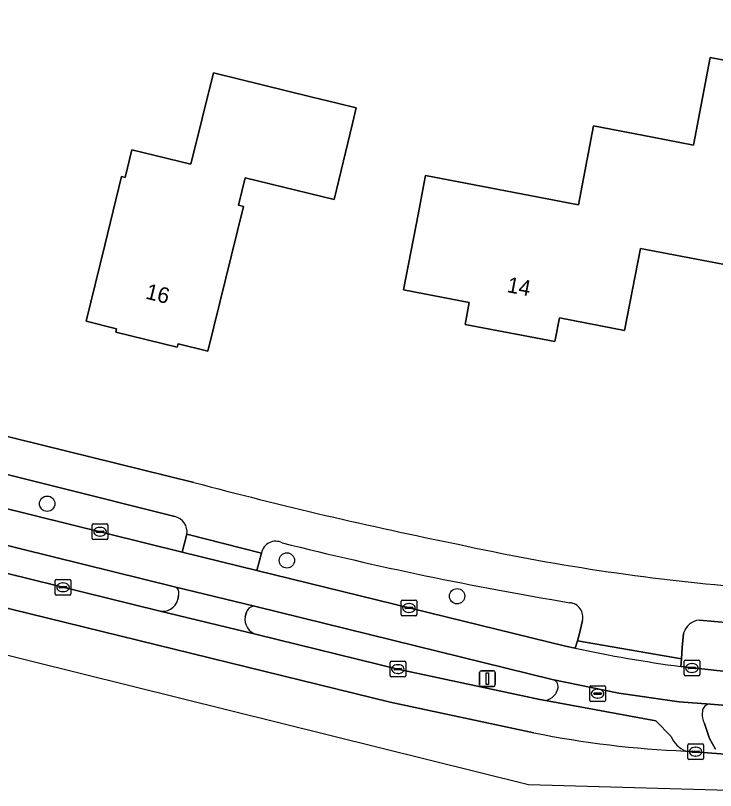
# Model space of a CAD drawing. Extents: x 161347 to 161881, y 382161 to 382804.
# Drawn here: x 161529.3 to 161573.93, y 382161.25 to 382210.69 of the extents above; entities that cross this region are included whole.
import ezdxf

# ---------------------------------------------------------------- set-up
doc = ezdxf.new("R2010")
doc.units = 0
for name, color, linetype in [('IMGEO_Berm_groen', 7, 'Continuous'), ('IMGEO_Boom', 7, 'Continuous'), ('IMGEO_Erf', 7, 'Continuous'), ('IMGEO_Fietspad_gesloten', 7, 'Continuous'), ('IMGEO_Kolk', 7, 'Continuous'), ('IMGEO_Lichtmast', 7, 'Continuous'), ('IMGEO_Pand', 7, 'Continuous'), ('IMGEO_Pand_nummerreeks', 7, 'Continuous'), ('IMGEO_Parkeervlak_gesloten', 7, 'Continuous'), ('IMGEO_Rijbaan_lokaal_gesloten', 7, 'Continuous'), ('IMGEO_Rioolput', 7, 'Continuous'), ('IMGEO_Verkeerseiland_open', 7, 'Continuous'), ('IMGEO_Voetpad_open', 7, 'Continuous')]:
    doc.layers.add(name, color=color, linetype=linetype)

msp = doc.modelspace()

# ---------------------------------------------------------------- linework, layer by layer
at = {"layer": 'IMGEO_Berm_groen'}
for points in [[(161523.76, 382182.658), (161523.26, 382180.579), (161539.929, 382176.444), (161540.229, 382177.6)], [(161539.452, 382178.724), (161523.76, 382182.658)], [(161539.444, 382174.246), (161523.769, 382178.11)], [(161523.782, 382176.315), (161538.439, 382172.703)], [(161544.988, 382176.392), (161544.687, 382175.272), (161564.377, 382170.458), (161564.988, 382170.326), (161565.131, 382170.805), (161565.266, 382171.258), (161565.458, 382172.096)], [(161539.66, 382173.423), (161539.695, 382173.695)], [(161563.516, 382168.335), (161544.627, 382172.985)], [(161544.032, 382172.631), (161543.946, 382172.356)], [(161575.793, 382171.854), (161572.905, 382172.115)], [(161571.905, 382171.267), (161571.81, 382170.378), (161571.757, 382169.655), (161571.72, 382169.156), (161576.527, 382168.636), (161576.563, 382169.135), (161576.609, 382169.787), (161576.631, 382170.705)], [(161544.683, 382171.197), (161553.68, 382168.99), (161562.741, 382167.053), (161563.09, 382166.989)]]:
    msp.add_lwpolyline(points, dxfattribs=at)
for centre, radius, start, end in [((161539.245, 382177.75), 0.996, 351.3225, 77.9882), ((161545.893, 382176.228), 0.92, 62.9734, 169.7054), ((161602.441, 382400.592), 230.484, 255.90508, 260.56483), ((161539.305, 382173.85), 0.419, 338.2981, 70.6838), ((161538.669, 382173.708), 1.031, 257.1038, 343.9503), ((161564.552, 382172.302), 0.93, 347.1697, 83.4921), ((161544.517, 382172.492), 0.505, 77.4373, 164.0644), ((161544.932, 382172.169), 1.004, 169.2756, 255.6284), ((161573.004, 382170.985), 1.135, 94.9994, 165.5965), ((161563.409, 382167.844), 0.503, 356.6377, 77.698), ((161562.887, 382168.012), 1.043, 281.2179, 349.0606)]:
    msp.add_arc(centre, radius, start, end, dxfattribs=at)
at = {"layer": 'IMGEO_Boom'}
for centre in [(161531.321, 382179.543), (161546.606, 382175.923), (161557.458, 382173.643)]:
    msp.add_circle(centre, 0.489, dxfattribs=at)
at = {"layer": 'IMGEO_Erf'}
msp.add_lwpolyline([(161420.378, 382210.687), (161464.013, 382199.817), (161500, 382190.938), (161540.678, 382180.901)], dxfattribs=at)
for points in [[(161577.039, 382198.776), (161575.33, 382199.104), (161574.504, 382194.801), (161569.143, 382195.829), (161568.139, 382190.598), (161563.988, 382191.395), (161563.698, 382189.886), (161557.969, 382190.985), (161558.235, 382192.373), (161554.045, 382193.177), (161554.988, 382198.088), (161555.341, 382199.93), (161555.448, 382200.485), (161565.196, 382198.605), (161566.163, 382203.645), (161569.916, 382202.925), (161572.525, 382202.424), (161573.599, 382208.016), (161577.829, 382207.204)], [(161549.617, 382198.942), (161543.945, 382200.333), (161543.516, 382198.584), (161543.836, 382198.505), (161541.572, 382189.278), (161539.668, 382189.745), (161539.615, 382189.531), (161535.693, 382190.494), (161535.745, 382190.707), (161533.802, 382191.184), (161534.993, 382196.041), (161536.065, 382200.41), (161536.289, 382200.356), (161536.723, 382202.124), (161540.492, 382201.2), (161541.922, 382207.028), (161548.222, 382205.483), (161549.805, 382205.095), (161551.032, 382204.794), (161550.792, 382203.802)]]:
    msp.add_lwpolyline(points, close=True, dxfattribs=at)
for centre, radius, start, end in [((161612.703, 382450.618), 279.168, 255.04873, 258.59958), ((161586.624, 382308.838), 135.053, 257.55552, 265.3213)]:
    msp.add_arc(centre, radius, start, end, dxfattribs=at)
at = {"layer": 'IMGEO_Fietspad_gesloten'}
for points in [[(161413.236, 382205.52), (161415.308, 382205.003), (161418.403, 382204.211), (161448.631, 382196.696), (161453.454, 382195.498), (161462.581, 382193.233), (161478.779, 382189.246), (161484.015, 382187.92), (161495.709, 382185.028), (161500, 382183.961), (161501.342, 382183.627), (161519.01, 382179.306), (161523.769, 382178.11), (161539.444, 382174.246), (161544.627, 382172.985), (161563.516, 382168.335), (161567.78, 382167.465), (161571.619, 382166.9), (161573.608, 382166.754), (161575.893, 382166.568), (161576.527, 382168.636), (161571.72, 382169.156)], [(161564.988, 382170.326), (161564.377, 382170.458), (161544.687, 382175.272), (161539.929, 382176.444), (161523.26, 382180.579), (161517.367, 382182.012), (161501.233, 382185.995)]]:
    msp.add_lwpolyline(points, dxfattribs=at)
msp.add_arc((161583.507, 382256.929), 88.561, 257.92979, 262.35153, dxfattribs=at)
at = {"layer": 'IMGEO_Kolk'}
for p, q in [((161534.194, 382177.329), (161534.194, 382178.181)), ((161534.269, 382178.255), (161535.121, 382178.255)), ((161535.195, 382178.181), (161535.195, 382177.329)), ((161534.453, 382177.749), (161534.453, 382177.761)), ((161534.891, 382177.712), (161534.493, 382177.712)), ((161534.496, 382177.798), (161534.894, 382177.798)), ((161534.682, 382178.035), (161534.707, 382178.035)), ((161534.937, 382177.761), (161534.937, 382177.749)), ((161535.121, 382177.255), (161534.269, 382177.255)), ((161534.705, 382177.475), (161534.68, 382177.475)), ((161531.908, 382174.711), (161532.76, 382174.711)), ((161531.833, 382173.785), (161531.833, 382174.637)), ((161532.092, 382174.205), (161532.092, 382174.217)), ((161532.135, 382174.254), (161532.533, 382174.254)), ((161532.321, 382174.491), (161532.346, 382174.491)), ((161532.576, 382174.217), (161532.576, 382174.205)), ((161532.834, 382174.637), (161532.834, 382173.785)), ((161532.76, 382173.711), (161531.908, 382173.711)), ((161532.53, 382174.168), (161532.132, 382174.168)), ((161532.344, 382173.931), (161532.319, 382173.931)), ((161553.888, 382172.464), (161553.888, 382173.316)), ((161553.963, 382173.39), (161554.815, 382173.39)), ((161554.889, 382173.316), (161554.889, 382172.464)), ((161554.147, 382172.884), (161554.147, 382172.896)), ((161554.585, 382172.847), (161554.187, 382172.847)), ((161554.19, 382172.933), (161554.588, 382172.933)), ((161554.376, 382173.17), (161554.401, 382173.17)), ((161554.631, 382172.896), (161554.631, 382172.884)), ((161554.815, 382172.39), (161553.963, 382172.39)), ((161554.399, 382172.61), (161554.374, 382172.61)), ((161553.183, 382168.565), (161553.183, 382169.417)), ((161553.258, 382169.491), (161554.11, 382169.491)), ((161553.671, 382169.271), (161553.696, 382169.271)), ((161554.184, 382169.417), (161554.184, 382168.565)), ((161571.93, 382168.638), (161571.93, 382169.49)), ((161572.005, 382169.564), (161572.857, 382169.564)), ((161572.418, 382169.344), (161572.443, 382169.344)), ((161572.931, 382169.49), (161572.931, 382168.638)), ((161553.442, 382168.985), (161553.442, 382168.997)), ((161553.88, 382168.948), (161553.482, 382168.948)), ((161553.485, 382169.034), (161553.883, 382169.034)), ((161553.926, 382168.997), (161553.926, 382168.985)), ((161572.189, 382169.058), (161572.189, 382169.07)), ((161572.627, 382169.021), (161572.229, 382169.021)), ((161572.232, 382169.107), (161572.63, 382169.107)), ((161572.441, 382168.784), (161572.416, 382168.784)), ((161572.673, 382169.07), (161572.673, 382169.058)), ((161554.11, 382168.491), (161553.258, 382168.491)), ((161553.694, 382168.711), (161553.669, 382168.711)), ((161572.857, 382168.564), (161572.005, 382168.564)), ((161572.163, 382163.297), (161572.163, 382164.149)), ((161572.238, 382164.223), (161573.09, 382164.223)), ((161572.651, 382164.003), (161572.676, 382164.003)), ((161573.164, 382164.149), (161573.164, 382163.297)), ((161572.422, 382163.717), (161572.422, 382163.729)), ((161572.86, 382163.68), (161572.462, 382163.68)), ((161572.465, 382163.766), (161572.863, 382163.766)), ((161572.674, 382163.443), (161572.649, 382163.443)), ((161572.906, 382163.729), (161572.906, 382163.717)), ((161573.09, 382163.223), (161572.238, 382163.223))]:
    msp.add_line(p, q, dxfattribs=at)
for points in [[(161534.194, 382177.329), (161534.194, 382178.181)], [(161534.269, 382178.255), (161535.121, 382178.255)], [(161535.195, 382178.181), (161535.195, 382177.329)], [(161535.121, 382177.255), (161534.269, 382177.255)], [(161531.908, 382174.711), (161532.76, 382174.711)], [(161531.833, 382173.785), (161531.833, 382174.637)], [(161532.834, 382174.637), (161532.834, 382173.785)], [(161532.76, 382173.711), (161531.908, 382173.711)], [(161553.888, 382172.464), (161553.888, 382173.316)], [(161553.963, 382173.39), (161554.815, 382173.39)], [(161554.889, 382173.316), (161554.889, 382172.464)], [(161554.815, 382172.39), (161553.963, 382172.39)], [(161553.183, 382168.565), (161553.183, 382169.417)], [(161553.258, 382169.491), (161554.11, 382169.491)], [(161554.184, 382169.417), (161554.184, 382168.565)], [(161571.93, 382168.638), (161571.93, 382169.49)], [(161572.005, 382169.564), (161572.857, 382169.564)], [(161572.931, 382169.49), (161572.931, 382168.638)], [(161554.11, 382168.491), (161553.258, 382168.491)], [(161572.857, 382168.564), (161572.005, 382168.564)], [(161572.163, 382163.297), (161572.163, 382164.149)], [(161572.238, 382164.223), (161573.09, 382164.223)], [(161573.164, 382164.149), (161573.164, 382163.297)], [(161573.09, 382163.223), (161572.238, 382163.223)]]:
    msp.add_lwpolyline(points, dxfattribs=at)
for centre, radius, start, end in [((161534.271, 382178.179), 0.0765, 91.552, 178.448), ((161534.271, 382178.179), 0.0765, 91.552, 178.448), ((161535.119, 382178.179), 0.0765, 1.552, 88.448), ((161535.119, 382178.179), 0.0765, 1.552, 88.448), ((161534.493, 382177.758), 0.0403, 85.8775, 175.7526), ((161534.49, 382177.748), 0.0366, 178.938, 274.7102), ((161534.894, 382177.755), 0.043, 264.8664, 352.4533), ((161534.898, 382177.76), 0.0386, 1.7309, 96.639), ((161534.271, 382177.331), 0.0765, 181.552, 268.448), ((161534.271, 382177.331), 0.0765, 181.552, 268.448), ((161535.119, 382177.331), 0.0765, 271.552, 358.448), ((161535.119, 382177.331), 0.0765, 271.552, 358.448), ((161531.91, 382174.635), 0.0765, 91.552, 178.448), ((161531.91, 382174.635), 0.0765, 91.552, 178.448), ((161532.758, 382174.635), 0.0765, 1.552, 88.448), ((161532.758, 382174.635), 0.0765, 1.552, 88.448), ((161532.132, 382174.214), 0.0403, 85.8775, 175.7526), ((161532.129, 382174.204), 0.0366, 178.938, 274.7102), ((161532.533, 382174.211), 0.043, 264.8664, 352.4533), ((161532.537, 382174.216), 0.0386, 1.7309, 96.639), ((161531.91, 382173.787), 0.0765, 181.552, 268.448), ((161531.91, 382173.787), 0.0765, 181.552, 268.448), ((161532.758, 382173.787), 0.0765, 271.552, 358.448), ((161532.758, 382173.787), 0.0765, 271.552, 358.448), ((161553.965, 382173.314), 0.0765, 91.552, 178.448), ((161553.965, 382173.314), 0.0765, 91.552, 178.448), ((161554.813, 382173.314), 0.0765, 1.552, 88.448), ((161554.813, 382173.314), 0.0765, 1.552, 88.448), ((161554.187, 382172.893), 0.0403, 85.8775, 175.7526), ((161554.184, 382172.883), 0.0366, 178.938, 274.7102), ((161554.588, 382172.89), 0.043, 264.8664, 352.4533), ((161554.592, 382172.895), 0.0386, 1.7309, 96.639), ((161553.965, 382172.466), 0.0765, 181.552, 268.448), ((161553.965, 382172.466), 0.0765, 181.552, 268.448), ((161554.813, 382172.466), 0.0765, 271.552, 358.448), ((161554.813, 382172.466), 0.0765, 271.552, 358.448), ((161553.26, 382169.415), 0.0765, 91.552, 178.448), ((161553.26, 382169.415), 0.0765, 91.552, 178.448), ((161554.108, 382169.415), 0.0765, 1.552, 88.448), ((161554.108, 382169.415), 0.0765, 1.552, 88.448), ((161572.007, 382169.488), 0.0765, 91.552, 178.448), ((161572.007, 382169.488), 0.0765, 91.552, 178.448), ((161572.855, 382169.488), 0.0765, 1.552, 88.448), ((161572.855, 382169.488), 0.0765, 1.552, 88.448), ((161553.482, 382168.994), 0.0403, 85.8775, 175.7526), ((161553.479, 382168.984), 0.0366, 178.938, 274.7102), ((161553.883, 382168.991), 0.043, 264.8664, 352.4533), ((161553.887, 382168.996), 0.0386, 1.7309, 96.639), ((161572.229, 382169.067), 0.0403, 85.8775, 175.7526), ((161572.226, 382169.057), 0.0366, 178.938, 274.7102), ((161572.63, 382169.064), 0.043, 264.8664, 352.4533), ((161572.634, 382169.069), 0.0386, 1.7309, 96.639), ((161553.26, 382168.567), 0.0765, 181.552, 268.448), ((161553.26, 382168.567), 0.0765, 181.552, 268.448), ((161554.108, 382168.567), 0.0765, 271.552, 358.448), ((161554.108, 382168.567), 0.0765, 271.552, 358.448), ((161572.007, 382168.64), 0.0765, 181.552, 268.448), ((161572.007, 382168.64), 0.0765, 181.552, 268.448), ((161572.855, 382168.64), 0.0765, 271.552, 358.448), ((161572.855, 382168.64), 0.0765, 271.552, 358.448), ((161572.24, 382164.147), 0.0765, 91.552, 178.448), ((161572.24, 382164.147), 0.0765, 91.552, 178.448), ((161573.088, 382164.147), 0.0765, 1.552, 88.448), ((161573.088, 382164.147), 0.0765, 1.552, 88.448), ((161572.462, 382163.726), 0.0403, 85.8775, 175.7526), ((161572.459, 382163.716), 0.0366, 178.938, 274.7102), ((161572.863, 382163.723), 0.043, 264.8664, 352.4533), ((161572.867, 382163.728), 0.0386, 1.7309, 96.639), ((161572.24, 382163.299), 0.0765, 181.552, 268.448), ((161572.24, 382163.299), 0.0765, 181.552, 268.448), ((161573.088, 382163.299), 0.0765, 271.552, 358.448), ((161573.088, 382163.299), 0.0765, 271.552, 358.448)]:
    msp.add_arc(centre, radius, start, end, dxfattribs=at)
for centre, major_axis, ratio, start_param, end_param in [((161534.681, 382177.755), (-0.387, 0.002), 0.722429, 4.712389, 7.853982), ((161534.706, 382177.755), (-0.39, 0.002), 0.717154, 1.570796, 4.712389), ((161532.32, 382174.211), (-0.387, 0.002), 0.722429, 4.712389, 7.853982), ((161532.345, 382174.211), (-0.39, 0.002), 0.717154, 1.570796, 4.712389), ((161554.375, 382172.89), (-0.387, 0.002), 0.722429, 4.712389, 7.853982), ((161554.4, 382172.89), (-0.39, 0.002), 0.717154, 1.570796, 4.712389), ((161553.67, 382168.991), (-0.387, 0.002), 0.722429, 4.712389, 7.853982), ((161553.695, 382168.991), (-0.39, 0.002), 0.717154, 1.570796, 4.712389), ((161572.417, 382169.064), (-0.387, 0.002), 0.722429, 4.712389, 7.853982), ((161572.442, 382169.064), (-0.39, 0.002), 0.717154, 1.570796, 4.712389), ((161572.65, 382163.723), (-0.387, 0.002), 0.722429, 4.712389, 7.853982), ((161572.675, 382163.723), (-0.39, 0.002), 0.717154, 1.570796, 4.712389)]:
    msp.add_ellipse(centre, major_axis=major_axis, ratio=ratio, start_param=start_param, end_param=end_param, dxfattribs=at)
at = {"layer": 'IMGEO_Lichtmast'}
for p, q in [((161558.897, 382167.98), (161558.897, 382168.78)), ((161558.897, 382168.78), (161558.897, 382167.98)), ((161558.997, 382168.88), (161559.787, 382168.88)), ((161559.787, 382168.88), (161558.997, 382168.88)), ((161559.887, 382168.78), (161559.887, 382167.98)), ((161559.887, 382167.98), (161559.887, 382168.78)), ((161559.787, 382167.88), (161558.997, 382167.88)), ((161558.997, 382167.88), (161559.787, 382167.88))]:
    msp.add_line(p, q, dxfattribs=at)
msp.add_lwpolyline([(161559.317, 382168.755), (161559.467, 382168.755), (161559.467, 382168.005), (161559.317, 382168.005), (161559.317, 382168.755)], dxfattribs=at)
for centre, start, end in [((161558.997, 382168.78), 90, 180), ((161558.997, 382168.78), 90, 180), ((161559.787, 382168.78), 0, 90), ((161559.787, 382168.78), 360, 90), ((161558.997, 382167.98), 180, 270), ((161558.997, 382167.98), 180, 270), ((161559.787, 382167.98), 270, 0), ((161559.787, 382167.98), 270, 0)]:
    msp.add_arc(centre, 0.1, start, end, dxfattribs=at)
at = {"layer": 'IMGEO_Pand'}
for points in [[(161554.988, 382198.088), (161554.045, 382193.177), (161558.235, 382192.373), (161557.969, 382190.985), (161563.698, 382189.886), (161563.988, 382191.395), (161568.139, 382190.598), (161569.143, 382195.829), (161574.504, 382194.801), (161575.33, 382199.104), (161577.039, 382198.776), (161577.829, 382207.204), (161573.599, 382208.016), (161572.525, 382202.424), (161569.916, 382202.925), (161566.163, 382203.645), (161565.196, 382198.605), (161555.448, 382200.485), (161555.341, 382199.93)], [(161541.922, 382207.028), (161540.492, 382201.2), (161536.723, 382202.124), (161536.289, 382200.356), (161536.065, 382200.41), (161534.993, 382196.041), (161533.802, 382191.184), (161535.745, 382190.707), (161535.693, 382190.494), (161539.615, 382189.531), (161539.668, 382189.745), (161541.572, 382189.278), (161543.836, 382198.505), (161543.516, 382198.584), (161543.945, 382200.333), (161549.617, 382198.942), (161550.792, 382203.802), (161551.032, 382204.794), (161549.805, 382205.095), (161548.222, 382205.483)]]:
    msp.add_lwpolyline(points, close=True, dxfattribs=at)
at = {"layer": 'IMGEO_Parkeervlak_gesloten'}
for points in [[(161571.104, 382164.701), (161570.133, 382165.693), (161563.09, 382166.989), (161562.741, 382167.053), (161553.68, 382168.99), (161544.683, 382171.197), (161538.439, 382172.703), (161523.782, 382176.315), (161518.095, 382177.712), (161501.466, 382181.829), (161500, 382182.195), (161494.84, 382183.482), (161484.029, 382186.14), (161477.906, 382187.637), (161453.562, 382193.718), (161447.783, 382195.136), (161430.279, 382199.461), (161429.995, 382199.482), (161429.682, 382199.431), (161427.287, 382198.569)], [(161425.904, 382198.493), (161453.047, 382191.62), (161517.576, 382175.615), (161553.188, 382166.887), (161562.35, 382164.929)]]:
    msp.add_lwpolyline(points, dxfattribs=at)
for centre, radius, start, end in [((161574.476, 382224.786), 61.073, 258.54755, 267.7053), ((161572.654, 382165.304), 1.663, 201.2563, 248.0068)]:
    msp.add_arc(centre, radius, start, end, dxfattribs=at)
at = {"layer": 'IMGEO_Rijbaan_lokaal_gesloten'}
for points in [[(161562.35, 382164.929), (161553.188, 382166.887), (161517.576, 382175.615), (161453.047, 382191.62), (161425.904, 382198.493)], [(161415.973, 382197.911), (161562.018, 382161.64), (161575.538, 382161.247)], [(161575.538, 382161.247), (161575.763, 382163.482), (161574.561, 382163.554), (161572.031, 382163.762)]]:
    msp.add_lwpolyline(points, dxfattribs=at)
msp.add_arc((161574.476, 382224.786), 61.073, 258.54755, 267.7053, dxfattribs=at)
at = {"layer": 'IMGEO_Rioolput'}
for p, q in [((161565.918, 382166.998), (161565.918, 382167.85)), ((161565.993, 382167.924), (161566.845, 382167.924)), ((161566.919, 382167.85), (161566.919, 382166.998)), ((161566.177, 382167.418), (161566.177, 382167.43)), ((161566.615, 382167.381), (161566.217, 382167.381)), ((161566.22, 382167.467), (161566.618, 382167.467)), ((161566.406, 382167.704), (161566.431, 382167.704)), ((161566.661, 382167.43), (161566.661, 382167.418)), ((161566.845, 382166.924), (161565.993, 382166.924)), ((161566.429, 382167.144), (161566.404, 382167.144))]:
    msp.add_line(p, q, dxfattribs=at)
for points in [[(161565.918, 382166.998), (161565.918, 382167.85)], [(161565.993, 382167.924), (161566.845, 382167.924)], [(161566.919, 382167.85), (161566.919, 382166.998)], [(161566.845, 382166.924), (161565.993, 382166.924)]]:
    msp.add_lwpolyline(points, dxfattribs=at)
for centre, radius, start, end in [((161565.995, 382167.848), 0.0765, 91.552, 178.448), ((161565.995, 382167.848), 0.0765, 91.552, 178.448), ((161566.843, 382167.848), 0.0765, 1.552, 88.448), ((161566.843, 382167.848), 0.0765, 1.552, 88.448), ((161566.217, 382167.427), 0.0403, 85.8775, 175.7526), ((161566.214, 382167.417), 0.0366, 178.938, 274.7102), ((161566.618, 382167.424), 0.043, 264.8664, 352.4533), ((161566.622, 382167.429), 0.0386, 1.7309, 96.639), ((161565.995, 382167), 0.0765, 181.552, 268.448), ((161565.995, 382167), 0.0765, 181.552, 268.448), ((161566.843, 382167), 0.0765, 271.552, 358.448), ((161566.843, 382167), 0.0765, 271.552, 358.448)]:
    msp.add_arc(centre, radius, start, end, dxfattribs=at)
for centre, major_axis, ratio, start_param, end_param in [((161566.405, 382167.424), (-0.387, 0.002), 0.722429, 4.712389, 7.853982), ((161566.43, 382167.424), (-0.39, 0.002), 0.717154, 1.570796, 4.712389)]:
    msp.add_ellipse(centre, major_axis=major_axis, ratio=ratio, start_param=start_param, end_param=end_param, dxfattribs=at)
at = {"layer": 'IMGEO_Verkeerseiland_open'}
for points in [[(161575.893, 382166.568), (161573.608, 382166.754)], [(161573.224, 382165.519), (161573.556, 382164.562), (161573.935, 382163.889)]]:
    msp.add_lwpolyline(points, dxfattribs=at)
for centre, radius, start, end in [((161574.424, 382166.105), 1.335, 172.5065, 206.0267), ((161573.582, 382166.273), 0.482, 86.9023, 179.2523)]:
    msp.add_arc(centre, radius, start, end, dxfattribs=at)
at = {"layer": 'IMGEO_Voetpad_open'}
for points in [[(161540.678, 382180.901), (161500, 382190.938), (161464.013, 382199.817)], [(161502.505, 382187.939), (161517.888, 382184.124), (161523.76, 382182.658), (161539.452, 382178.724)], [(161540.229, 382177.6), (161544.988, 382176.392)], [(161544.627, 382172.985), (161539.444, 382174.246)], [(161539.695, 382173.695), (161539.66, 382173.423)], [(161538.439, 382172.703), (161544.683, 382171.197)], [(161543.946, 382172.356), (161544.032, 382172.631)], [(161565.458, 382172.096), (161565.266, 382171.258), (161565.131, 382170.805), (161571.757, 382169.655), (161571.81, 382170.378), (161571.905, 382171.267)], [(161572.905, 382172.115), (161575.793, 382171.854)], [(161571.72, 382169.156), (161571.757, 382169.655), (161565.131, 382170.805), (161564.988, 382170.326)], [(161573.608, 382166.754), (161571.619, 382166.9), (161567.78, 382167.465), (161563.516, 382168.335)], [(161563.09, 382166.989), (161570.133, 382165.693), (161571.104, 382164.701)], [(161573.935, 382163.889), (161573.556, 382164.562), (161573.224, 382165.519)], [(161572.031, 382163.762), (161574.561, 382163.554)]]:
    msp.add_lwpolyline(points, dxfattribs=at)
msp.add_lwpolyline([(161539.929, 382176.444), (161544.687, 382175.272), (161544.988, 382176.392), (161540.229, 382177.6)], close=True, dxfattribs=at)
for centre, radius, start, end in [((161612.703, 382450.618), 279.168, 255.04873, 258.59958), ((161539.245, 382177.75), 0.996, 351.3225, 77.9882), ((161545.893, 382176.228), 0.92, 62.9734, 169.7054), ((161602.441, 382400.592), 230.484, 255.90508, 260.56483), ((161586.624, 382308.838), 135.053, 257.55552, 265.3213), ((161539.305, 382173.85), 0.419, 338.2981, 70.6838), ((161538.669, 382173.708), 1.031, 257.1038, 343.9503), ((161564.552, 382172.302), 0.93, 347.1697, 83.4921), ((161544.517, 382172.492), 0.505, 77.4373, 164.0644), ((161544.932, 382172.169), 1.004, 169.2756, 255.6284), ((161573.004, 382170.985), 1.135, 94.9994, 165.5965), ((161583.507, 382256.929), 88.561, 257.92979, 262.35153), ((161563.409, 382167.844), 0.503, 356.6377, 77.698), ((161562.887, 382168.012), 1.043, 281.2179, 349.0606), ((161574.424, 382166.105), 1.335, 172.5065, 206.0267), ((161573.582, 382166.273), 0.482, 86.9023, 179.2523), ((161572.654, 382165.304), 1.663, 201.2563, 248.0068)]:
    msp.add_arc(centre, radius, start, end, dxfattribs=at)

# ---------------------------------------------------------------- texts
at = {"layer": 'IMGEO_Pand_nummerreeks'}
for s, rotation, p in [('14', 349.1424, (161560.586, 382193.05)), ('16', 346.2032, (161537.541, 382192.635))]:
    msp.add_text(s, height=1, rotation=rotation, dxfattribs=at).set_placement(p)

doc.saveas('drawing.dxf')
